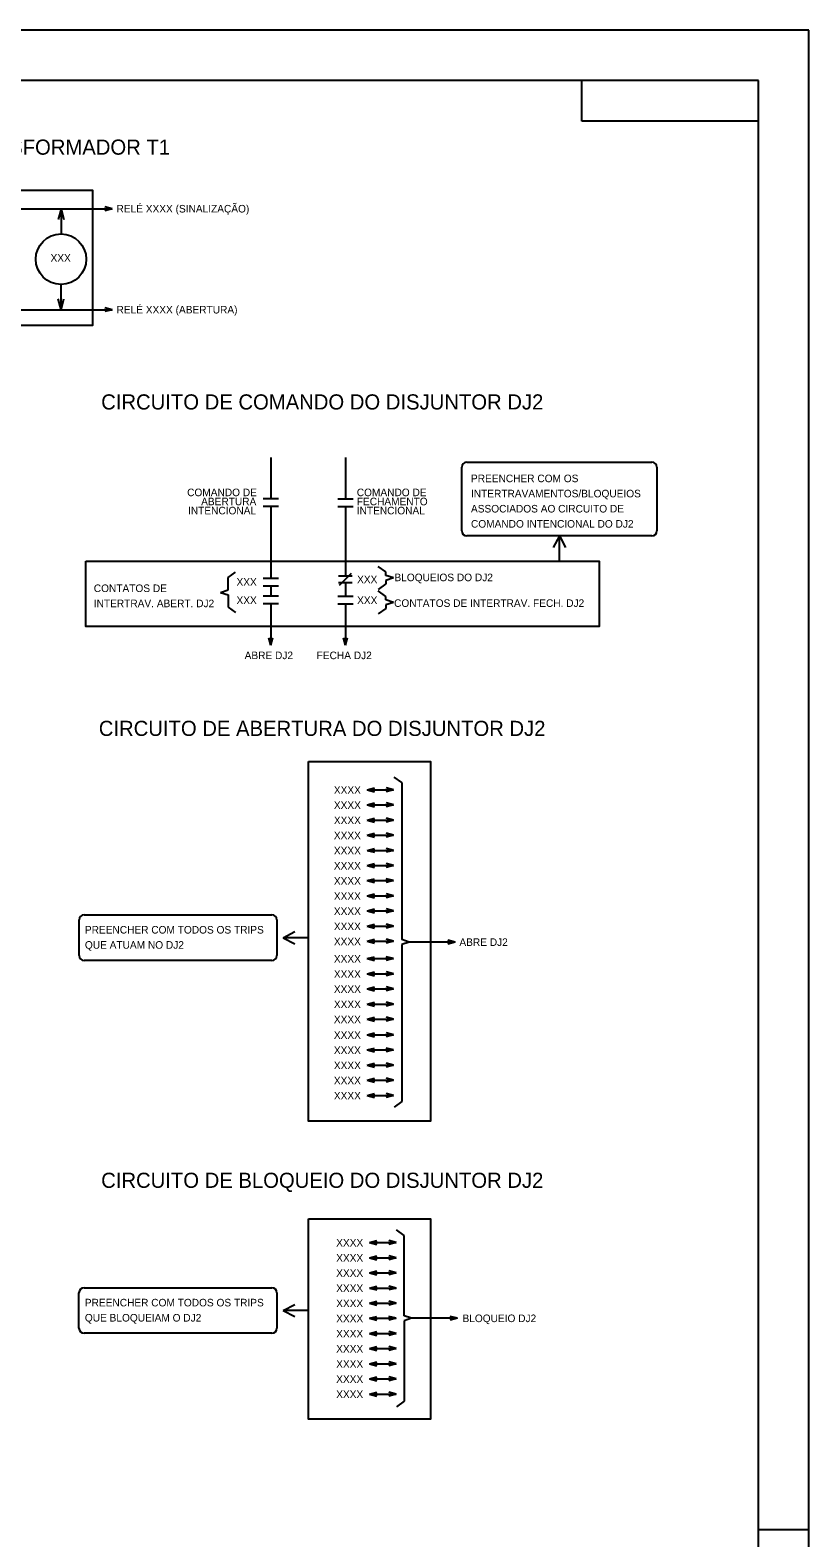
# Model space of a CAD drawing. Extents: x 563 to 1404, y 358 to 952.
# Drawn here: x 1249.3 to 1403.6, y 653.3 to 952 of the extents above; entities that cross this region are included whole.
import ezdxf

# ---------------------------------------------------------------- set-up
doc = ezdxf.new("R2010")
doc.units = 0
doc.layers.add('New Level (0)', color=7, linetype='Continuous')

# ---------------------------------------------------------------- blocks, each defined once
blk = doc.blocks.new('39')
for p, q in [((0, 0), (1.45, 0.39)), ((0, 0), (5.22, 0)), ((0, 0), (1.45, -0.39)), ((5.22, 0), (3.77, 0.39)), ((5.22, 0), (3.77, -0.39))]:
    blk.add_line(p, q)

msp = doc.modelspace()

# ---------------------------------------------------------------- linework, layer by layer
for p, q in [((1265.58, 916.59), (1264.13, 916.98)), ((1206.46, 916.59), (1265.58, 916.59)), ((1255.43, 916.59), (1254.85, 914.42)), ((1255.43, 916.59), (1255.43, 911.59)), ((1255.43, 916.59), (1256.01, 914.42)), ((1265.58, 916.59), (1264.13, 916.2)), ((1255.43, 896.59), (1255.43, 901.59)), ((1243.19, 896.59), (1265.58, 896.59)), ((1255.43, 896.59), (1254.85, 898.77)), ((1255.43, 896.59), (1256.01, 898.77)), ((1265.58, 896.59), (1264.13, 896.98)), ((1265.58, 896.59), (1264.13, 896.2)), ((1296.98, 867.28), (1296.98, 859.1)), ((1311.77, 867.28), (1311.77, 859.1)), ((1298.48, 859.1), (1295.48, 859.1)), ((1298.48, 857.6), (1295.48, 857.6)), ((1296.98, 857.6), (1296.98, 843.36)), ((1310.27, 859.1), (1313.27, 859.1)), ((1310.27, 857.6), (1313.27, 857.6)), ((1311.77, 857.6), (1311.77, 843.86)), ((1319.78, 844.64), (1318.28, 845.72)), ((1288.52, 843.55), (1290.02, 844.63)), ((1288.52, 841.08), (1288.52, 843.55)), ((1298.48, 843.36), (1295.48, 843.36)), ((1310.42, 843.86), (1313.12, 843.86)), ((1313.12, 842.51), (1310.42, 842.51)), ((1310.58, 842), (1312.97, 844.38)), ((1311.77, 842.36), (1311.77, 839.86)), ((1319.78, 842.27), (1318.28, 841.19)), ((1319.78, 843.96), (1319.78, 844.64)), ((1321.28, 843.46), (1319.78, 843.96)), ((1321.28, 843.46), (1319.78, 842.96)), ((1319.78, 842.96), (1319.78, 842.27)), ((1287.02, 840.58), (1288.52, 841.08)), ((1287.02, 840.58), (1288.52, 840.08)), ((1288.52, 840.08), (1288.52, 837.68)), ((1298.48, 841.86), (1295.48, 841.86)), ((1298.48, 839.86), (1295.48, 839.86)), ((1296.98, 841.86), (1296.98, 839.86)), ((1310.27, 839.86), (1313.27, 839.86)), ((1310.27, 839.86), (1313.27, 839.86)), ((1319.78, 839.78), (1318.28, 840.87)), ((1319.78, 839.1), (1319.78, 839.78)), ((1288.52, 837.68), (1290.02, 836.6)), ((1298.48, 838.36), (1295.48, 838.36)), ((1296.98, 838.36), (1296.98, 830.12)), ((1310.27, 838.36), (1313.27, 838.36)), ((1310.27, 838.36), (1313.27, 838.36)), ((1311.77, 838.36), (1311.77, 830.12)), ((1319.78, 837.42), (1318.28, 836.33)), ((1321.28, 838.6), (1319.78, 839.1)), ((1321.28, 838.6), (1319.78, 838.1)), ((1319.78, 838.1), (1319.78, 837.42)), ((1296.98, 830.12), (1296.59, 831.57)), ((1296.98, 830.12), (1297.37, 831.57)), ((1311.77, 830.12), (1311.38, 831.57)), ((1311.77, 830.12), (1312.16, 831.57)), ((1322.92, 802.92), (1321.42, 804)), ((1316.1, 801.5), (1317.55, 801.89)), ((1316.1, 801.5), (1321.32, 801.5)), ((1316.1, 801.5), (1317.55, 801.11)), ((1321.32, 801.5), (1319.87, 801.89)), ((1321.32, 801.5), (1319.87, 801.11)), ((1322.92, 802.92), (1322.92, 771.82)), ((1316.1, 798.5), (1317.55, 798.89)), ((1316.1, 798.5), (1321.32, 798.5)), ((1316.1, 798.5), (1317.55, 798.11)), ((1321.32, 798.5), (1319.87, 798.89)), ((1321.32, 798.5), (1319.87, 798.11)), ((1316.1, 795.5), (1317.55, 795.89)), ((1316.1, 795.5), (1321.32, 795.5)), ((1316.1, 795.5), (1317.55, 795.11)), ((1321.32, 795.5), (1319.87, 795.89)), ((1321.32, 795.5), (1319.87, 795.11)), ((1324.42, 771.32), (1322.92, 771.82)), ((1324.42, 771.32), (1322.92, 770.82)), ((1322.92, 770.82), (1322.92, 739.73)), ((1333.48, 771.32), (1324.42, 771.32)), ((1333.48, 771.32), (1332.03, 771.71)), ((1333.48, 771.32), (1332.03, 770.94)), ((1316.1, 768.06), (1317.55, 768.44)), ((1316.1, 768.06), (1321.32, 768.06)), ((1316.1, 768.06), (1317.55, 767.67)), ((1321.32, 768.06), (1319.87, 768.44)), ((1321.32, 768.06), (1319.87, 767.67)), ((1316.1, 752.96), (1317.55, 753.35)), ((1316.1, 752.96), (1321.32, 752.96)), ((1316.1, 752.96), (1317.55, 752.57)), ((1321.32, 752.96), (1319.87, 753.35)), ((1321.32, 752.96), (1319.87, 752.57)), ((1322.92, 739.73), (1321.42, 738.65)), ((1323.39, 713.23), (1321.89, 714.31)), ((1316.57, 711.81), (1318.02, 712.2)), ((1316.57, 711.81), (1321.79, 711.81)), ((1316.57, 711.81), (1318.02, 711.43)), ((1321.79, 711.81), (1320.34, 712.2)), ((1321.79, 711.81), (1320.34, 711.43)), ((1323.39, 697.31), (1323.39, 713.23)), ((1316.57, 705.81), (1318.02, 706.2)), ((1316.57, 705.81), (1321.79, 705.81)), ((1316.57, 705.81), (1318.02, 705.43)), ((1321.79, 705.81), (1320.34, 706.2)), ((1321.79, 705.81), (1320.34, 705.43)), ((1324.89, 696.81), (1323.39, 697.31)), ((1324.89, 696.81), (1323.39, 696.31)), ((1323.39, 696.31), (1323.39, 680.4)), ((1333.95, 696.81), (1324.89, 696.81)), ((1333.95, 696.81), (1332.5, 697.2)), ((1333.95, 696.81), (1332.5, 696.43)), ((1323.39, 680.4), (1321.89, 679.31))]:
    msp.add_line(p, q)
msp.add_circle((1255.43, 906.59), 5)
at = {"layer": 'New Level (0)'}
for p, q in [((1403.58, 951.96), (562.58, 951.96)), ((1403.58, 951.96), (562.58, 951.96)), ((1403.58, 357.96), (1403.58, 951.96)), ((1403.58, 357.96), (1403.58, 951.96)), ((1393.58, 941.96), (572.58, 941.96)), ((1358.58, 933.96), (1358.58, 941.96)), ((1393.58, 367.96), (1393.58, 941.96)), ((1393.58, 367.96), (1393.58, 941.96)), ((1393.58, 933.96), (1358.58, 933.96)), ((1335.83, 866.38), (1372.48, 866.38)), ((1334.83, 852.79), (1334.83, 865.38)), ((1373.48, 865.38), (1373.48, 852.79)), ((1372.48, 851.79), (1335.83, 851.79)), ((1354.15, 851.79), (1352.94, 849.49)), ((1354.15, 846.76), (1354.15, 851.79)), ((1354.15, 851.79), (1355.36, 849.49)), ((1259.99, 776.72), (1267.34, 776.72)), ((1267.34, 776.72), (1297.21, 776.72)), ((1258.99, 768.69), (1258.99, 775.72)), ((1298.21, 775.72), (1298.21, 768.69)), ((1299.45, 772.2), (1301.75, 773.41)), ((1304.48, 772.2), (1299.45, 772.2)), ((1299.45, 772.2), (1301.75, 770.99)), ((1297.21, 767.69), (1259.99, 767.69)), ((1258.98, 694.84), (1258.98, 701.87)), ((1259.98, 702.87), (1267.33, 702.87)), ((1267.33, 702.87), (1297.21, 702.87)), ((1298.21, 701.87), (1298.21, 694.84)), ((1299.45, 698.36), (1301.74, 699.57)), ((1304.48, 698.36), (1299.45, 698.36)), ((1299.45, 698.36), (1301.74, 697.15)), ((1297.21, 693.84), (1259.98, 693.84)), ((1393.58, 654.96), (1403.58, 654.96))]:
    msp.add_line(p, q, dxfattribs=at)
for points in [[(1197.77, 920.29), (1261.69, 920.29), (1261.69, 893.47), (1197.77, 893.47)], [(1260.35, 846.76), (1362.05, 846.76), (1362.05, 833.87), (1260.35, 833.87)], [(1304.48, 807.12), (1328.61, 807.12), (1328.61, 735.87), (1304.48, 735.87)], [(1304.48, 716.5), (1328.61, 716.5), (1328.61, 676.86), (1304.48, 676.86)]]:
    msp.add_lwpolyline(points, close=True, dxfattribs=at)
for centre, start, end in [((1335.83, 865.38), 90, 180), ((1372.48, 865.38), 0, 90), ((1335.83, 852.79), 180, 270), ((1372.48, 852.79), 270, 0), ((1259.99, 775.72), 90, 180), ((1297.21, 775.72), 0, 90), ((1259.99, 768.69), 180, 270), ((1297.21, 768.69), 270, 0), ((1259.98, 701.87), 90, 180), ((1297.21, 701.87), 0, 90), ((1259.98, 694.84), 180, 270), ((1297.21, 694.84), 270, 0)]:
    msp.add_arc(centre, 1, start, end, dxfattribs=at)

# ---------------------------------------------------------------- block references
for p in [(1316.1, 792.5), (1316.1, 789.5), (1316.1, 786.5), (1316.1, 783.5), (1316.1, 780.5), (1316.1, 777.5), (1316.1, 774.5), (1316.1, 771.5), (1316.1, 765.06), (1316.1, 762.06), (1316.1, 759.06), (1316.1, 756.06), (1316.1, 749.96), (1316.1, 746.96), (1316.1, 743.96), (1316.1, 740.96), (1316.57, 708.81), (1316.57, 702.81), (1316.57, 699.81), (1316.57, 696.81), (1316.57, 693.81), (1316.57, 690.81), (1316.57, 687.81), (1316.57, 684.81), (1316.57, 681.81)]:
    msp.add_blockref('39', p)

# ---------------------------------------------------------------- texts
for s, height, p in [('SINALIZAÇÃO TRANSFORMADOR T1', 3, (1206.59, 927.29)), ('RELÉ XXXX (SINALIZAÇÃO)', 1.5, (1266.42, 915.84)), ('XXX', 1.5, (1253.35, 906.09)), ('RELÉ XXXX (ABERTURA)', 1.5, (1266.42, 895.84)), ('CIRCUITO DE COMANDO DO DISJUNTOR DJ2', 3, (1263.38, 876.82)), ('PREENCHER COM OS ', 1.5, (1336.64, 862.42)), ('COMANDO DE', 1.5, (1280.41, 859.65)), ('COMANDO DE ', 1.5, (1314.02, 859.65)), ('INTERTRAVAMENTOS/BLOQUEIOS', 1.5, (1336.64, 859.42)), (' INTENCIONAL', 1.5, (1280.03, 856.05)), (' ABERTURA', 1.5, (1282.63, 857.85)), ('FECHAMENTO ', 1.5, (1314.02, 857.85)), ('INTENCIONAL', 1.5, (1314.02, 856.05)), ('ASSOCIADOS AO CIRCUITO DE ', 1.5, (1336.64, 856.42)), ('COMANDO INTENCIONAL DO DJ2', 1.5, (1336.64, 853.42)), ('CONTATOS DE ', 1.5, (1261.92, 840.66)), ('XXX', 1.5, (1290.19, 841.92)), ('XXX', 1.5, (1314.08, 842.41)), ('BLOQUEIOS DO DJ2', 1.5, (1321.48, 842.81)), ('INTERTRAV. ABERT. DJ2', 1.5, (1261.92, 837.66)), ('XXX', 1.5, (1290.19, 838.29)), ('XXX', 1.5, (1314.08, 838.29)), ('CONTATOS DE INTERTRAV. FECH. DJ2', 1.5, (1321.41, 837.72)), ('ABRE DJ2', 1.5, (1291.8, 827.37)), ('FECHA DJ2', 1.5, (1306.07, 827.37)), ('CIRCUITO DE ABERTURA DO DISJUNTOR DJ2', 3, (1262.91, 812.16)), ('XXXX', 1.5, (1309.48, 800.7)), ('XXXX', 1.5, (1309.48, 797.7)), ('XXXX', 1.5, (1309.48, 794.7)), ('XXXX', 1.5, (1309.48, 791.7)), ('XXXX', 1.5, (1309.48, 788.7)), ('XXXX', 1.5, (1309.48, 785.7)), ('XXXX', 1.5, (1309.48, 782.7)), ('XXXX', 1.5, (1309.48, 779.7)), ('XXXX', 1.5, (1309.48, 776.7)), ('PREENCHER COM TODOS OS TRIPS', 1.5, (1260.16, 773.02)), ('XXXX', 1.5, (1309.48, 773.7)), ('QUE ATUAM NO DJ2', 1.5, (1260.16, 770.02)), ('XXXX', 1.5, (1309.48, 770.7)), ('ABRE DJ2', 1.5, (1334.35, 770.57)), ('XXXX', 1.5, (1309.48, 767.26)), ('XXXX', 1.5, (1309.48, 764.26)), ('XXXX', 1.5, (1309.48, 761.26)), ('XXXX', 1.5, (1309.48, 758.26)), ('XXXX', 1.5, (1309.48, 755.26)), ('XXXX', 1.5, (1309.48, 752.16)), ('XXXX', 1.5, (1309.48, 749.16)), ('XXXX', 1.5, (1309.48, 746.16)), ('XXXX', 1.5, (1309.48, 743.16)), ('XXXX', 1.5, (1309.48, 740.16)), ('CIRCUITO DE BLOQUEIO DO DISJUNTOR DJ2', 3, (1263.38, 722.65)), ('XXXX', 1.5, (1309.94, 711.02)), ('XXXX', 1.5, (1309.94, 708.02)), ('XXXX', 1.5, (1309.94, 705.02)), ('XXXX', 1.5, (1309.94, 702.02)), ('PREENCHER COM TODOS OS TRIPS', 1.5, (1260.15, 699.17)), ('XXXX', 1.5, (1309.94, 699.02)), ('QUE BLOQUEIAM O DJ2', 1.5, (1260.15, 696.17)), ('XXXX', 1.5, (1309.94, 696.02)), ('BLOQUEIO DJ2', 1.5, (1334.96, 696.06)), ('XXXX', 1.5, (1309.94, 693.02)), ('XXXX', 1.5, (1309.94, 690.02)), ('XXXX', 1.5, (1309.94, 687.02)), ('XXXX', 1.5, (1309.94, 684.02)), ('XXXX', 1.5, (1309.94, 681.02))]:
    msp.add_text(s, height=height).set_placement(p)

doc.saveas('drawing.dxf')
